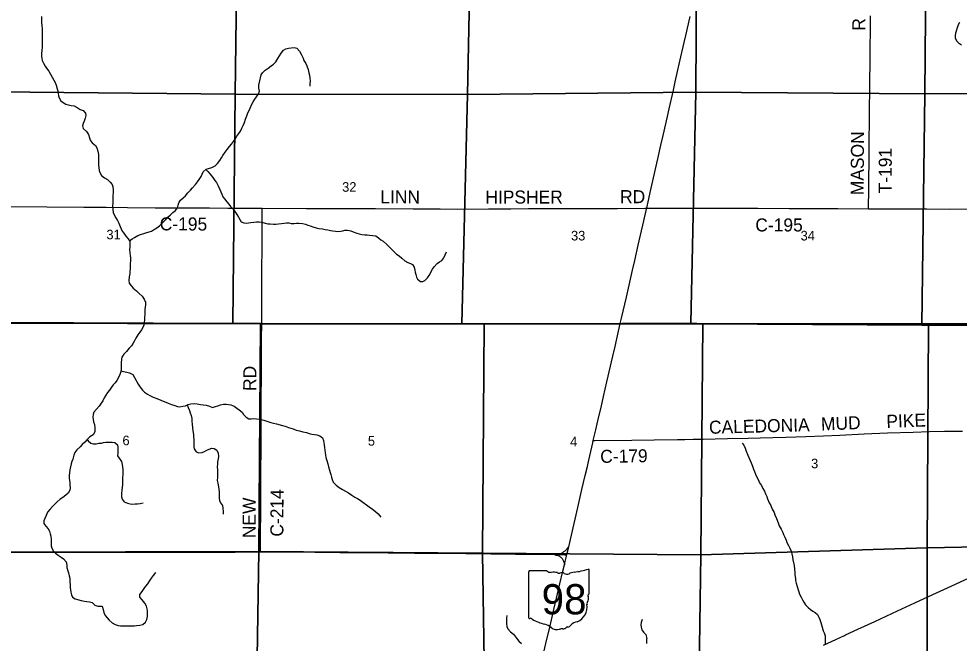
# Model space of a CAD drawing. Extents: x 1584893 to 1934202, y 663575 to 1091909.
# Drawn here: x 1809965 to 1831624, y 956462 to 970849 of the extents above; entities that cross this region are included whole.
import ezdxf

# ---------------------------------------------------------------- set-up
doc = ezdxf.new("R2010")
doc.units = 0
for name, color, linetype in [('GM_X_County_Road', 7, 'Continuous'), ('GM_X_County_Road_Text', 7, 'Continuous'), ('GM_X_Minor_River', 7, 'Continuous'), ('GM_X_Section', 7, 'Continuous'), ('GM_X_Section_Text', 7, 'Continuous'), ('GM_X_State_Location', 7, 'Continuous'), ('GM_X_State_Route', 7, 'Continuous'), ('GM_X_State_Shield', 7, 'Continuous'), ('GM_X_Township', 7, 'Continuous'), ('GM_X_Township_Road', 7, 'Continuous'), ('GM_X_Township_Road_Text', 7, 'Continuous')]:
    doc.layers.add(name, color=color, linetype=linetype)

msp = doc.modelspace()

# ---------------------------------------------------------------- linework, layer by layer
at = {"layer": 'GM_X_County_Road'}
for points in [[(1809411, 966526), (1809759, 966523), (1810612, 966517), (1811466, 966511), (1811974, 966507), (1812467, 966502), (1813107, 966497), (1813697, 966494), (1814354, 966491), (1814780, 966489), (1815519, 966487), (1815572, 966486)], [(1815562, 963840), (1815563, 963899), (1815563, 964310), (1815565, 964835), (1815570, 965804), (1815573, 966166), (1815572, 966445), (1815572, 966486)], [(1815572, 966486), (1816585, 966482), (1817189, 966480)], [(1817189, 966480), (1817242, 966480), (1817570, 966480), (1818177, 966477), (1819047, 966473), (1819670, 966468), (1820080, 966466), (1820786, 966470), (1821295, 966474), (1821705, 966475), (1822148, 966476), (1822394, 966476), (1822624, 966477), (1823001, 966478), (1823756, 966480), (1824380, 966484), (1824427, 966485)], [(1824427, 966485), (1824609, 966486), (1825134, 966488), (1825380, 966488), (1825809, 966487), (1826283, 966485), (1826792, 966483), (1826988, 966483), (1827710, 966477), (1828104, 966477), (1828826, 966475), (1829537, 966472)], [(1829537, 966472), (1829663, 966471), (1830204, 966469), (1830877, 966467), (1831402, 966466), (1832059, 966467), (1832189, 966467)], [(1815528, 958564), (1815529, 958595), (1815530, 958628), (1815532, 958793), (1815537, 959679), (1815539, 960090), (1815546, 961272), (1815547, 961633), (1815550, 962110), (1815553, 962619), (1815553, 962898), (1815556, 963275), (1815555, 963473), (1815558, 963620), (1815559, 963678), (1815561, 963735), (1815562, 963840)], [(1823197, 961132), (1823233, 961132), (1824087, 961142), (1824595, 961149), (1825137, 961155), (1825301, 961156), (1825497, 961160), (1825727, 961164), (1826006, 961169), (1826285, 961177), (1826760, 961190), (1827039, 961197), (1827334, 961204), (1827630, 961213), (1828089, 961226), (1828499, 961239), (1828876, 961256), (1829433, 961283), (1829974, 961306), (1830564, 961327), (1830941, 961339), (1831286, 961346), (1831401, 961348), (1831696, 961351)], [(1822307, 958505), (1822317, 958509), (1822329, 958511), (1822349, 958513), (1822366, 958515), (1822394, 958519), (1822411, 958522), (1822427, 958526), (1822446, 958532), (1822464, 958540), (1822478, 958547), (1822493, 958555), (1822521, 958572), (1822535, 958582), (1822548, 958592), (1822571, 958614), (1822592, 958640), (1822630, 958684)], [(1809356, 958554), (1809631, 958555), (1810238, 958557), (1810960, 958558), (1811354, 958558), (1811714, 958558), (1812764, 958560), (1813158, 958561), (1813715, 958563), (1813813, 958563), (1813953, 958563), (1814060, 958563), (1814945, 958563), (1815241, 958564), (1815528, 958564)], [(1815528, 958564), (1815667, 958564), (1816061, 958565), (1816339, 958564), (1816782, 958560), (1817127, 958557), (1817356, 958555), (1817619, 958553), (1818078, 958549), (1818471, 958545), (1818799, 958542), (1819078, 958540), (1819587, 958536), (1820259, 958530), (1820833, 958525), (1821030, 958522), (1821407, 958517), (1821669, 958512), (1821964, 958510), (1822307, 958505)], [(1822307, 958505), (1822407, 958503), (1822539, 958498), (1822555, 958497), (1822586, 958495)], [(1822307, 958505), (1822311, 958501), (1822315, 958499), (1822326, 958497), (1822337, 958494), (1822349, 958492), (1822366, 958487), (1822385, 958481), (1822405, 958472), (1822419, 958465), (1822433, 958456), (1822446, 958446), (1822459, 958435), (1822470, 958424), (1822481, 958411), (1822490, 958398), (1822498, 958383), (1822505, 958368), (1822511, 958353), (1822513, 958347), (1822518, 958331), (1822522, 958315), (1822530, 958279), (1822533, 958269)]]:
    msp.add_lwpolyline(points, dxfattribs=at)
at = {"layer": 'GM_X_Minor_River'}
for points in [[(1810487, 970905), (1810486, 970845), (1810491, 970759), (1810494, 970705), (1810501, 970614), (1810502, 970548), (1810504, 970480), (1810505, 970424), (1810506, 970353), (1810505, 970283), (1810500, 970191), (1810495, 970127), (1810490, 970041), (1810490, 969991), (1810497, 969938), (1810507, 969888), (1810534, 969826), (1810573, 969761), (1810601, 969710), (1810654, 969642), (1810699, 969573), (1810774, 969436), (1810799, 969385), (1810824, 969321), (1810851, 969236), (1810865, 969186), (1810872, 969132), (1810881, 969077), (1810893, 969027), (1810932, 968958), (1810988, 968920), (1811047, 968885), (1811111, 968866), (1811173, 968855), (1811241, 968847), (1811309, 968808), (1811378, 968759)], [(1831629, 970761), (1831602, 970708), (1831580, 970642), (1831557, 970568), (1831540, 970516), (1831531, 970464), (1831534, 970412), (1831564, 970343), (1831607, 970292), (1831680, 970247)], [(1812511, 965731), (1812575, 965778), (1812629, 965810), (1812708, 965859), (1812768, 965880), (1812823, 965898), (1812891, 965915), (1812967, 965938), (1813020, 965958), (1813070, 965983), (1813143, 966030), (1813207, 966082), (1813268, 966143), (1813351, 966227), (1813400, 966280), (1813459, 966332), (1813513, 966383), (1813564, 966427), (1813617, 966492), (1813632, 966554), (1813650, 966608), (1813689, 966672), (1813750, 966725), (1813802, 966773), (1813861, 966842), (1813918, 966898), (1813969, 966956), (1814032, 967035), (1814079, 967095), (1814119, 967146), (1814162, 967216), (1814185, 967268), (1814215, 967320), (1814284, 967385), (1814335, 967403), (1814409, 967420), (1814490, 967465), (1814540, 967518), (1814593, 967584), (1814634, 967644), (1814665, 967696), (1814718, 967777), (1814764, 967835), (1814817, 967904), (1814862, 967960), (1814907, 968022), (1814950, 968079), (1814990, 968143), (1815033, 968207), (1815068, 968262), (1815105, 968328), (1815134, 968392), (1815160, 968462), (1815189, 968536), (1815218, 968612), (1815243, 968682), (1815268, 968740), (1815293, 968793), (1815336, 968881), (1815366, 968937), (1815401, 968995), (1815440, 969054), (1815483, 969124), (1815505, 969182), (1815490, 969252), (1815497, 969323), (1815512, 969387), (1815550, 969555), (1815581, 969606), (1815641, 969668), (1815712, 969711), (1815779, 969762), (1815835, 969804), (1815888, 969860), (1815933, 969935), (1815968, 969997), (1816005, 970061), (1816058, 970130), (1816114, 970154), (1816174, 970171), (1816236, 970180), (1816309, 970188), (1816372, 970169), (1816432, 970102), (1816467, 970033), (1816514, 969946), (1816533, 969890), (1816575, 969821), (1816602, 969769), (1816629, 969680), (1816648, 969608), (1816659, 969550), (1816671, 969481), (1816674, 969423), (1816671, 969351), (1816666, 969295)], [(1811378, 968759), (1811444, 968740), (1811500, 968675), (1811509, 968619), (1811496, 968557), (1811467, 968491), (1811451, 968439), (1811436, 968383), (1811449, 968319), (1811523, 968256), (1811574, 968183), (1811597, 968104), (1811610, 968052), (1811654, 967991), (1811731, 967928), (1811764, 967876), (1811784, 967799), (1811797, 967719), (1811802, 967653), (1811803, 967600), (1811803, 967548), (1811804, 967478), (1811807, 967420), (1811818, 967352), (1811836, 967293), (1811871, 967239), (1811942, 967184), (1812008, 967143), (1812068, 967086), (1812117, 967031), (1812134, 966977), (1812140, 966909), (1812135, 966842), (1812134, 966776), (1812131, 966702), (1812132, 966648), (1812128, 966598), (1812125, 966534), (1812128, 966453), (1812141, 966383), (1812165, 966333), (1812200, 966266), (1812235, 966205), (1812267, 966141), (1812296, 966066), (1812325, 966012), (1812347, 965959), (1812382, 965909), (1812433, 965840), (1812483, 965781), (1812520, 965715), (1812523, 965640), (1812522, 965588), (1812518, 965530), (1812523, 965458), (1812530, 965398), (1812535, 965339), (1812535, 965277), (1812532, 965203), (1812531, 965149), (1812528, 965083), (1812526, 965033), (1812521, 964979), (1812510, 964905), (1812499, 964820), (1812505, 964758), (1812560, 964691), (1812599, 964641), (1812673, 964580), (1812734, 964523), (1812803, 964458), (1812853, 964387), (1812882, 964319), (1812881, 964262), (1812873, 964208), (1812870, 964150), (1812869, 964092), (1812866, 964034), (1812864, 963978), (1812861, 963918), (1812852, 963844), (1812842, 963790), (1812819, 963736), (1812788, 963682), (1812753, 963626), (1812707, 963566), (1812664, 963489), (1812631, 963427), (1812602, 963375), (1812557, 963317), (1812507, 963260), (1812442, 963186), (1812383, 963121), (1812340, 963055), (1812329, 963003), (1812324, 962923), (1812326, 962847), (1812323, 962781), (1812312, 962715), (1812293, 962651), (1812262, 962587)], [(1814275, 967376), (1814318, 967333), (1814373, 967266), (1814434, 967189), (1814480, 967126), (1814515, 967074), (1814560, 967003), (1814593, 966916), (1814617, 966862), (1814638, 966809), (1814667, 966749), (1814705, 966698), (1814754, 966635), (1814804, 966579), (1814843, 966528), (1814900, 966463), (1814938, 966411), (1814987, 966340), (1815028, 966275), (1815054, 966225), (1815087, 966170), (1815147, 966148), (1815207, 966143), (1815257, 966148), (1815307, 966158), (1815381, 966165), (1815442, 966170), (1815502, 966169), (1815566, 966161), (1815639, 966138), (1815697, 966127), (1815754, 966128), (1815830, 966120), (1815886, 966121), (1815944, 966122), (1816012, 966129), (1816076, 966141), (1816132, 966148), (1816182, 966145), (1816240, 966131), (1816308, 966130), (1816359, 966141), (1816417, 966143), (1816497, 966130), (1816565, 966117), (1816622, 966096), (1816678, 966076), (1816736, 966055), (1816812, 966034), (1816878, 966019), (1816960, 966006), (1817024, 965995), (1817084, 965985), (1817142, 965974), (1817194, 965963), (1817260, 965954), (1817316, 965946), (1817372, 965953), (1817426, 965966), (1817476, 965980), (1817538, 965979), (1817610, 965964), (1817668, 965944), (1817748, 965909), (1817804, 965892), (1817864, 965879), (1817932, 965872), (1817986, 965868), (1818046, 965863), (1818116, 965860), (1818186, 965849), (1818253, 965806), (1818307, 965760), (1818359, 965725), (1818440, 965652), (1818499, 965597), (1818553, 965536), (1818667, 965426), (1818723, 965386), (1818790, 965335), (1818856, 965270), (1818925, 965235), (1818983, 965212), (1819035, 965185), (1819072, 965123), (1819090, 965060), (1819097, 965008), (1819108, 964954), (1819122, 964898), (1819149, 964847), (1819215, 964794), (1819269, 964796), (1819319, 964817), (1819376, 964883), (1819429, 964956), (1819462, 965024), (1819490, 965082), (1819529, 965138), (1819598, 965211), (1819657, 965246), (1819707, 965282)], [(1819707, 965282), (1819758, 965343), (1819787, 965413), (1819814, 965481)], [(1812316, 962737), (1812380, 962726), (1812452, 962709), (1812518, 962690), (1812588, 962655), (1812631, 962587), (1812713, 962433), (1812760, 962360), (1812812, 962290), (1812863, 962243), (1812931, 962200), (1812984, 962169), (1813062, 962130), (1813144, 962097), (1813234, 962062), (1813289, 962039), (1813353, 962019), (1813409, 961996), (1813479, 961965), (1813557, 961938), (1813618, 961917), (1813672, 961911), (1813745, 961922), (1813801, 961935), (1813867, 961960), (1813924, 961978), (1814004, 961985), (1814070, 961974), (1814150, 961959), (1814208, 961954), (1814280, 961950), (1814354, 961925), (1814427, 961894), (1814496, 961913), (1814550, 961934), (1814612, 961958), (1814679, 961967), (1814743, 961968), (1814793, 961964), (1814847, 961953), (1814928, 961922), (1814984, 961881), (1815042, 961840), (1815111, 961782), (1815144, 961731), (1815198, 961668), (1815263, 961633), (1815317, 961631), (1815374, 961636), (1815438, 961635), (1815498, 961627), (1815550, 961618), (1815612, 961601), (1815703, 961572), (1815773, 961547), (1815835, 961530), (1815901, 961516), (1816041, 961478), (1816101, 961463), (1816178, 961434), (1816284, 961401), (1816352, 961374), (1816432, 961355), (1816508, 961334), (1816588, 961315), (1816649, 961294), (1816711, 961279), (1816773, 961271), (1816827, 961260), (1816897, 961241), (1816961, 961194), (1816980, 961134), (1816987, 961084), (1816997, 961029), (1817004, 960975), (1817011, 960913), (1817021, 960851), (1817026, 960800), (1817037, 960738), (1817057, 960672), (1817080, 960595), (1817101, 960523), (1817124, 960448), (1817139, 960398), (1817151, 960346), (1817168, 960287), (1817180, 960237), (1817207, 960171), (1817274, 960100), (1817346, 960049), (1817421, 960004), (1817487, 959967), (1817556, 959926), (1817638, 959875), (1817706, 959828), (1817769, 959793), (1817827, 959760), (1817886, 959711), (1817972, 959650), (1818037, 959603), (1818109, 959552)], [(1812262, 962587), (1812220, 962519), (1812185, 962465), (1812140, 962414), (1812103, 962358), (1812055, 962294), (1812006, 962235), (1811969, 962179), (1811934, 962113), (1811899, 962049), (1811863, 961990), (1811814, 961924), (1811753, 961855), (1811696, 961787), (1811679, 961733), (1811673, 961673), (1811678, 961619), (1811689, 961566), (1811707, 961498), (1811718, 961422), (1811719, 961329), (1811676, 961266), (1811603, 961216), (1811538, 961159), (1811484, 961098), (1811423, 961042), (1811376, 960988), (1811305, 960921), (1811258, 960857), (1811236, 960794), (1811208, 960706), (1811188, 960652), (1811171, 960596), (1811154, 960524), (1811137, 960460), (1811124, 960327), (1811129, 960265), (1811133, 960213), (1811138, 960163), (1811143, 960111), (1811151, 960042), (1811142, 959990), (1811105, 959923), (1811048, 959871), (1810980, 959818), (1810921, 959780), (1810852, 959723), (1810802, 959673), (1810743, 959612), (1810680, 959546), (1810627, 959479), (1810594, 959407), (1810563, 959339), (1810545, 959285), (1810542, 959223), (1810591, 959162), (1810645, 959098), (1810674, 959045), (1810685, 958985), (1810701, 958926), (1810710, 958852), (1810713, 958782), (1810710, 958706), (1810727, 958655), (1810767, 958585), (1810810, 958534), (1810872, 958493), (1810941, 958446), (1810995, 958407), (1811054, 958339), (1811071, 958262), (1811073, 958208), (1811092, 958132), (1811107, 958081), (1811124, 958013), (1811138, 957959), (1811143, 957880), (1811146, 957808), (1811151, 957746), (1811162, 957641), (1811181, 957573), (1811205, 957521), (1811260, 957486), (1811314, 957471), (1811404, 957450), (1811480, 957431), (1811534, 957422), (1811594, 957414), (1811652, 957397), (1811717, 957342), (1811783, 957317), (1811833, 957315), (1811887, 957318), (1811910, 957238), (1811924, 957169), (1811953, 957099), (1811998, 957044), (1812050, 956991), (1812117, 956932), (1812183, 956891), (1812250, 956871)], [(1813845, 961952), (1813863, 961894), (1813896, 961826), (1813915, 961771), (1813938, 961705), (1813952, 961637), (1813953, 961568), (1813958, 961510), (1813965, 961426), (1813976, 961353), (1813985, 961271), (1813991, 961217), (1813994, 961165), (1813993, 961109), (1813997, 961054), (1813998, 960996), (1814005, 960938), (1814047, 960871), (1814112, 960848), (1814185, 960858), (1814241, 960879), (1814295, 960908), (1814346, 960932), (1814414, 960953), (1814468, 960945), (1814524, 960908), (1814557, 960839), (1814564, 960765), (1814557, 960711), (1814545, 960645), (1814538, 960589), (1814537, 960529), (1814540, 960458), (1814542, 960400), (1814541, 960342), (1814538, 960290), (1814537, 960210), (1814547, 960147), (1814562, 960069), (1814573, 960011), (1814578, 959942), (1814578, 959872), (1814581, 959804), (1814584, 959750), (1814611, 959693), (1814653, 959637), (1814668, 959564), (1814669, 959508), (1814673, 959438)], [(1811536, 961156), (1811562, 961125), (1811625, 961068), (1811677, 961057), (1811745, 961058), (1811808, 961068), (1811868, 961075), (1811918, 961084), (1811970, 961092), (1812040, 961095), (1812114, 961092), (1812180, 961083), (1812238, 961035), (1812247, 960976), (1812248, 960902), (1812244, 960844), (1812235, 960780), (1812278, 960727), (1812327, 960650), (1812349, 960578), (1812356, 960528), (1812365, 960456), (1812365, 960403), (1812360, 960347), (1812355, 960271), (1812354, 960167), (1812351, 960109), (1812348, 960055), (1812340, 959986), (1812331, 959912), (1812334, 959834), (1812347, 959784), (1812395, 959719), (1812470, 959686), (1812530, 959673), (1812582, 959667), (1812642, 959670), (1812702, 959675), (1812759, 959685), (1812827, 959694)], [(1826625, 961073), (1826662, 961022), (1826694, 960954), (1826719, 960885), (1826758, 960794), (1826779, 960738), (1826812, 960669), (1826834, 960615), (1826861, 960542), (1826888, 960476), (1826912, 960419), (1826935, 960359), (1826954, 960307), (1826992, 960238), (1827025, 960161), (1827070, 960097), (1827101, 960028), (1827141, 959968), (1827166, 959901), (1827197, 959840), (1827208, 959788), (1827245, 959698), (1827285, 959637), (1827318, 959548), (1827359, 959470), (1827374, 959417), (1827413, 959337), (1827454, 959236), (1827481, 959167), (1827525, 959088), (1827558, 959014), (1827579, 958964), (1827605, 958903), (1827636, 958838), (1827653, 958782), (1827690, 958717), (1827726, 958651), (1827757, 958580), (1827770, 958520), (1827781, 958454), (1827795, 958381), (1827825, 958253), (1827832, 958168), (1827835, 958098), (1827839, 958040), (1827852, 957955), (1827857, 957905), (1827870, 957847), (1827891, 957770), (1827915, 957694), (1827934, 957644), (1827947, 957593), (1827981, 957525), (1828014, 957464), (1828045, 957406), (1828085, 957349), (1828144, 957282), (1828198, 957239), (1828253, 957199), (1828305, 957166), (1828358, 957123), (1828390, 957059), (1828411, 957006), (1828434, 956942), (1828454, 956883), (1828467, 956833), (1828494, 956748), (1828516, 956698), (1828539, 956630), (1828540, 956527)], [(1818109, 959552), (1818182, 959497), (1818240, 959444), (1818303, 959369)], [(1812250, 956871), (1812306, 956862), (1812371, 956863), (1812453, 956862), (1812531, 956859), (1812627, 956862), (1812677, 956870), (1812755, 956881), (1812824, 956894), (1812886, 956947), (1812911, 957011), (1812926, 957081), (1812929, 957146), (1812927, 957206), (1812920, 957256), (1812909, 957312), (1812870, 957387), (1812810, 957458), (1812749, 957521), (1812756, 957587), (1812803, 957656), (1812855, 957722), (1812894, 957776), (1812937, 957829), (1812974, 957889), (1813025, 957963), (1813065, 958026), (1813118, 958094)], [(1821208, 957101), (1821201, 957037), (1821195, 956979), (1821198, 956908), (1821207, 956848), (1821232, 956794), (1821290, 956723), (1821355, 956668), (1821430, 956582)], [(1824325, 957012), (1824296, 956940), (1824294, 956886), (1824301, 956832), (1824318, 956770), (1824356, 956715), (1824409, 956664), (1824430, 956567)], [(1821430, 956582), (1821481, 956510), (1821546, 956455)], [(1824428, 956455), (1824428, 956511), (1824430, 956567)], [(1828540, 956527), (1828539, 956441)]]:
    msp.add_lwpolyline(points, dxfattribs=at)
at = {"layer": 'GM_X_Section'}
for points in [[(1809466, 974458), (1815015, 974433), (1814948, 969116), (1809423, 969163)], [(1815015, 974433), (1820407, 974408), (1820302, 969107), (1814948, 969116)], [(1820407, 974408), (1825590, 974426), (1825561, 969159), (1820302, 969107)], [(1825590, 974426), (1830875, 974457), (1830835, 969120), (1825561, 969159)], [(1830875, 974457), (1836118, 974458), (1836100, 969135), (1830835, 969120)], [(1809423, 969163), (1814948, 969116), (1814894, 963832), (1809383, 963850)], [(1814948, 969116), (1820302, 969107), (1820171, 963821), (1815534, 963828), (1814894, 963832)], [(1820302, 969107), (1825561, 969159), (1825444, 963834), (1820683, 963816), (1820171, 963821)], [(1825561, 969159), (1830835, 969120), (1830763, 963787), (1825722, 963820), (1825444, 963834)], [(1830835, 969120), (1836100, 969135), (1836085, 963804), (1836027, 963800), (1830913, 963783), (1830763, 963787)], [(1809383, 963850), (1814894, 963832), (1815534, 963828), (1815495, 958577), (1809340, 958559)], [(1815534, 963828), (1820171, 963821), (1820683, 963816), (1820644, 958537), (1815495, 958577)], [(1825444, 963834), (1825722, 963820), (1825675, 958497), (1820644, 958537), (1820683, 963816)], [(1825722, 963820), (1830763, 963787), (1830913, 963783), (1830887, 958663), (1825675, 958497)], [(1830913, 963783), (1836027, 963800), (1836044, 958759), (1830887, 958663)], [(1825675, 958497), (1830887, 958663), (1830886, 953288), (1825595, 953192)], [(1830887, 958663), (1836044, 958759), (1836103, 953387), (1830886, 953288)], [(1809340, 958559), (1815495, 958577), (1815412, 953201), (1809279, 953181)], [(1815495, 958577), (1820644, 958537), (1820731, 953108), (1815412, 953201)], [(1820644, 958537), (1825675, 958497), (1825595, 953192), (1820731, 953108)]]:
    msp.add_lwpolyline(points, close=True, dxfattribs=at)
at = {"layer": 'GM_X_State_Route'}
for points in [[(1821950, 955789), (1822129, 956554), (1822188, 956793), (1822291, 957241), (1822350, 957497), (1822429, 957832), (1822497, 958119), (1822533, 958269), (1822551, 958343), (1822586, 958495), (1822594, 958535), (1822630, 958684), (1822692, 958950), (1822839, 959590), (1822935, 960005), (1823010, 960325), (1823060, 960532), (1823077, 960610), (1823092, 960676), (1823184, 961076), (1823197, 961132), (1823255, 961379), (1823318, 961652), (1823374, 961891), (1823432, 962147), (1823510, 962483), (1823646, 963075), (1823698, 963298), (1823778, 963650), (1823818, 963827), (1823847, 963954), (1823958, 964434), (1824099, 965058), (1824150, 965282), (1824231, 965634), (1824360, 966194), (1824415, 966433), (1824424, 966470), (1824427, 966485), (1824444, 966566), (1824451, 966594), (1824508, 966850), (1824682, 967619), (1824755, 967938), (1824806, 968162), (1824903, 968595), (1824943, 968771), (1825040, 969203), (1825084, 969395), (1825139, 969635), (1825215, 969971), (1825291, 970307), (1825327, 970467), (1825424, 970899)], [(1828979, 956642), (1829007, 956655), (1829290, 956786), (1829678, 956965), (1830200, 957205), (1830602, 957391), (1831019, 957584), (1831273, 957700), (1831452, 957782), (1831839, 957962), (1832197, 958127), (1832205, 958130), (1832376, 958208), (1832579, 958301)], [(1828501, 956420), (1828784, 956551), (1828979, 956642)]]:
    msp.add_lwpolyline(points, dxfattribs=at)
at = {"layer": 'GM_X_State_Shield'}
for p, q in [((1821708, 958110), (1821708, 957053)), ((1822129, 958128), (1821722, 958128)), ((1823100, 957601), (1823100, 958154)), ((1823100, 957601), (1823100, 957601))]:
    msp.add_line(p, q, dxfattribs=at)
for centre, radius, start, end in [((1822604, 959568), 1476, 275.8445, 288.9065), ((1823085, 958156), 15.5, 351.8621, 97.738), ((1821724, 958112), 16.1, 98.1301, 188.1301), ((1822226, 958250), 156, 231.6195, 271.1119), ((1822278, 957534), 562, 80.4867, 94.9883), ((1822406, 958117), 45.1, 219.7921, 297.1024), ((1822472, 957995), 93.8, 54.4667, 119.1411), ((1822593, 958163), 113, 233.8562, 294.8282), ((1822792, 957805), 297, 97.3462, 120.7689), ((1823096, 957561), 24, 107.944, 210.337), ((1822944, 957491), 144, 340.033, 23.6496), ((1823083, 957599), 16.6, 289.6038, 7.7341), ((1822687, 957299), 369, 292.3089, 8.9858), ((1823156, 957370), 105, 136.8065, 186.9296), ((1821724, 957051), 16.3, 171.9584, 258.3066), ((1821726, 957159), 124, 267.339, 280.6039), ((1821752, 956992), 44.8, 29.7484, 93.2717), ((1822317, 957941), 1066, 240.4129, 257.1985), ((1821999, 956578), 334, 47.1842, 75.836), ((1822586, 956950), 119, 282.8732, 323.2771), ((1822842, 956756), 202, 94.4031, 142.5768), ((1822360, 956987), 212, 230.7004, 286.2918), ((1822482, 956621), 174, 85.6951, 111.2099), ((1822498, 956908), 113, 268.777, 315.5493), ((1822600, 956805), 31.8, 65.7517, 132.6484)]:
    msp.add_arc(centre, radius, start, end, dxfattribs=at)
at = {"layer": 'GM_X_Township'}
msp.add_lwpolyline([(1809388, 963837), (1809397, 965194), (1809409, 966524), (1809470, 974481), (1809490, 979763), (1809554, 985051), (1810918, 985033), (1820580, 985048), (1828627, 985061), (1836217, 985098), (1839819, 985043), (1841171, 985014), (1841533, 985009), (1841532, 984992), (1841496, 979677), (1841459, 974382), (1841436, 971009), (1841405, 966456), (1841387, 963824), (1839237, 963824), (1832077, 963824), (1823776, 963824), (1815539, 963824)], close=True, dxfattribs=at)
msp.add_lwpolyline([(1809298, 953687), (1809358, 958555), (1809388, 963837), (1815539, 963824), (1823776, 963824), (1832077, 963824), (1839237, 963824), (1841387, 963824), (1841392, 961182), (1841394, 960342), (1841397, 958575), (1841402, 956488), (1841392, 953202)], dxfattribs=at)
at = {"layer": 'GM_X_Township_Road'}
msp.add_lwpolyline([(1829537, 966472), (1829538, 966488), (1829542, 966920), (1829546, 967166), (1829549, 967543), (1829549, 967740), (1829551, 967921), (1829552, 968150), (1829555, 968380), (1829558, 968773), (1829564, 969216), (1829567, 969462), (1829572, 969806), (1829574, 969987), (1829577, 970282), (1829580, 970479), (1829580, 970659), (1829582, 970921)], dxfattribs=at)

# ---------------------------------------------------------------- texts
at = {"layer": 'GM_X_County_Road_Text'}
for s, rotation, p in [('LINN', 359.7122, (1818291, 966597)), ('HIPSHER', 0, (1820711, 966592)), ('RD', 0, (1823813, 966601)), ('C-195', 359.7247, (1813211, 965975)), ('C-195', 359.9968, (1826928, 965949)), ('RD', 89.5063, (1815432, 962273)), ('CALEDONIA', 1.5221, (1825865, 961286)), ('MUD', 2.3612, (1828446, 961361)), ('PIKE', 2.1667, (1829951, 961422)), ('C-179', 0.8259, (1823358, 960616)), ('C-214', 89.7247, (1816058, 958917)), ('NEW', 89.6986, (1815418, 958881))]:
    msp.add_text(s, height=300, rotation=rotation, dxfattribs=at).set_placement(p)
at = {"layer": 'GM_X_Section_Text'}
for s, p in [('32', (1817413, 966864)), ('31', (1811983, 965768)), ('33', (1822684, 965742)), ('34', (1827971, 965742)), ('6', (1812353, 961023)), ('5', (1818005, 961013)), ('4', (1822662, 960998)), ('3', (1828213, 960493))]:
    msp.add_text(s, height=221, rotation=0, dxfattribs=at).set_placement(p)
at = {"layer": 'GM_X_State_Location'}
for s in ['s', 'r']:
    msp.add_text(s, height=1, dxfattribs=at).set_placement((1822388, 957511))
msp.add_text('98', height=1, rotation=0, dxfattribs=at).set_placement((1822136, 957438))
at = {"layer": 'GM_X_State_Shield'}
msp.add_text('98', height=696.1, dxfattribs=at).set_placement((1822006, 957127))
at = {"layer": 'GM_X_Township_Road_Text'}
for s, rotation, p in [('R', 89.8985, (1829463, 970575)), ('MASON', 89.6216, (1829424, 966784)), ('T-191', 89.7193, (1830067, 966826))]:
    msp.add_text(s, height=300, rotation=rotation, dxfattribs=at).set_placement(p)

doc.saveas('drawing.dxf')
